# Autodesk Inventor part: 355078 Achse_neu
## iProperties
Created: 2006-10
Part Number: 355078 Achse_neu
Material: 1.4301
Description: Bolzen
Document SubType Name: Modeling
Designer: OSchmidt
Cost Center: 0,048 kg
Authority: 6093 mm^3
Density: 7.85 g/cm^3
Mass: 123.439 g
Surface Area: 56.8126 cm^2
Volume: 15.7248 cm^3
Abmessung: Rd. 10
HalbzeugNorm: DIN 671
Zweck: 266187
SaveDate: 2006-10-25
SaveTime: 23:52
TotalMass: 0,048 kg
TotalVolume: 6093 mm^3
Author: OSchmidt
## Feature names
1. Extrusion2
2. Extrusion4
3. Spiegeln2 [Mirror]
